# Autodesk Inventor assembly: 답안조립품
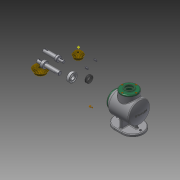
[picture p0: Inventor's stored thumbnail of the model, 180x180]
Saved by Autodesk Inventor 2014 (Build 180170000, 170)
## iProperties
Created: 2016-04
Part Number: 답안조립품
Document SubType Name: Assembly
Designer: USER
Author: USER
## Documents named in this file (14)
- C:\Users\USER\Desktop\460407V1005\답안조립품.iam
- C:\Users\USER\Desktop\460407V1005\본체.ipt
- C:\Users\USER\Desktop\460407V1005\M4.ipt
- C:\Users\USER\Desktop\460407V1005\메인 베벨기어.ipt
- C:\Users\USER\Desktop\460407V1005\메인 축.ipt
- 메인 축.ipt
- C:\Users\USER\Desktop\460407V1005\베어링 6203.ipt
- C:\Users\USER\Desktop\460407V1005\서브 베벨기어.ipt
- C:\Users\USER\Desktop\460407V1005\서브 축.ipt
- 서브 축.ipt
- C:\Users\USER\Desktop\460407V1005\오일실 17 32 8.ipt
- C:\Users\USER\Desktop\460407V1005\커버.ipt
- C:\Users\USER\Desktop\460407V1005\키 4x4.ipt
- C:\Users\USER\Desktop\460407V1005\키 5x5.ipt
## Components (5 placed, 1 different names)
1. M4:1
2. M4:2
3. M4:3
4. M4:4
5. M4:5
